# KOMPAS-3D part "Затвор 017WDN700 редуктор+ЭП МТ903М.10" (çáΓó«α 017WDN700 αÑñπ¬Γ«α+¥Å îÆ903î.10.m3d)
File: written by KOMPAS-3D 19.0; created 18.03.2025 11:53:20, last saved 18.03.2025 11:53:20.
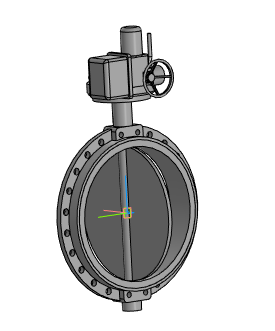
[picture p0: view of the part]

Document properties: Автор: Евгений; Полное имя файла: Затвор 017WDN700 редуктор+ЭП МТ903М.10.a3d

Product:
- Part/product: Затвор 017WDN700 редуктор+ЭП МТ903М.10
    Масса: 495.617

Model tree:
1. Операция без истории:1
